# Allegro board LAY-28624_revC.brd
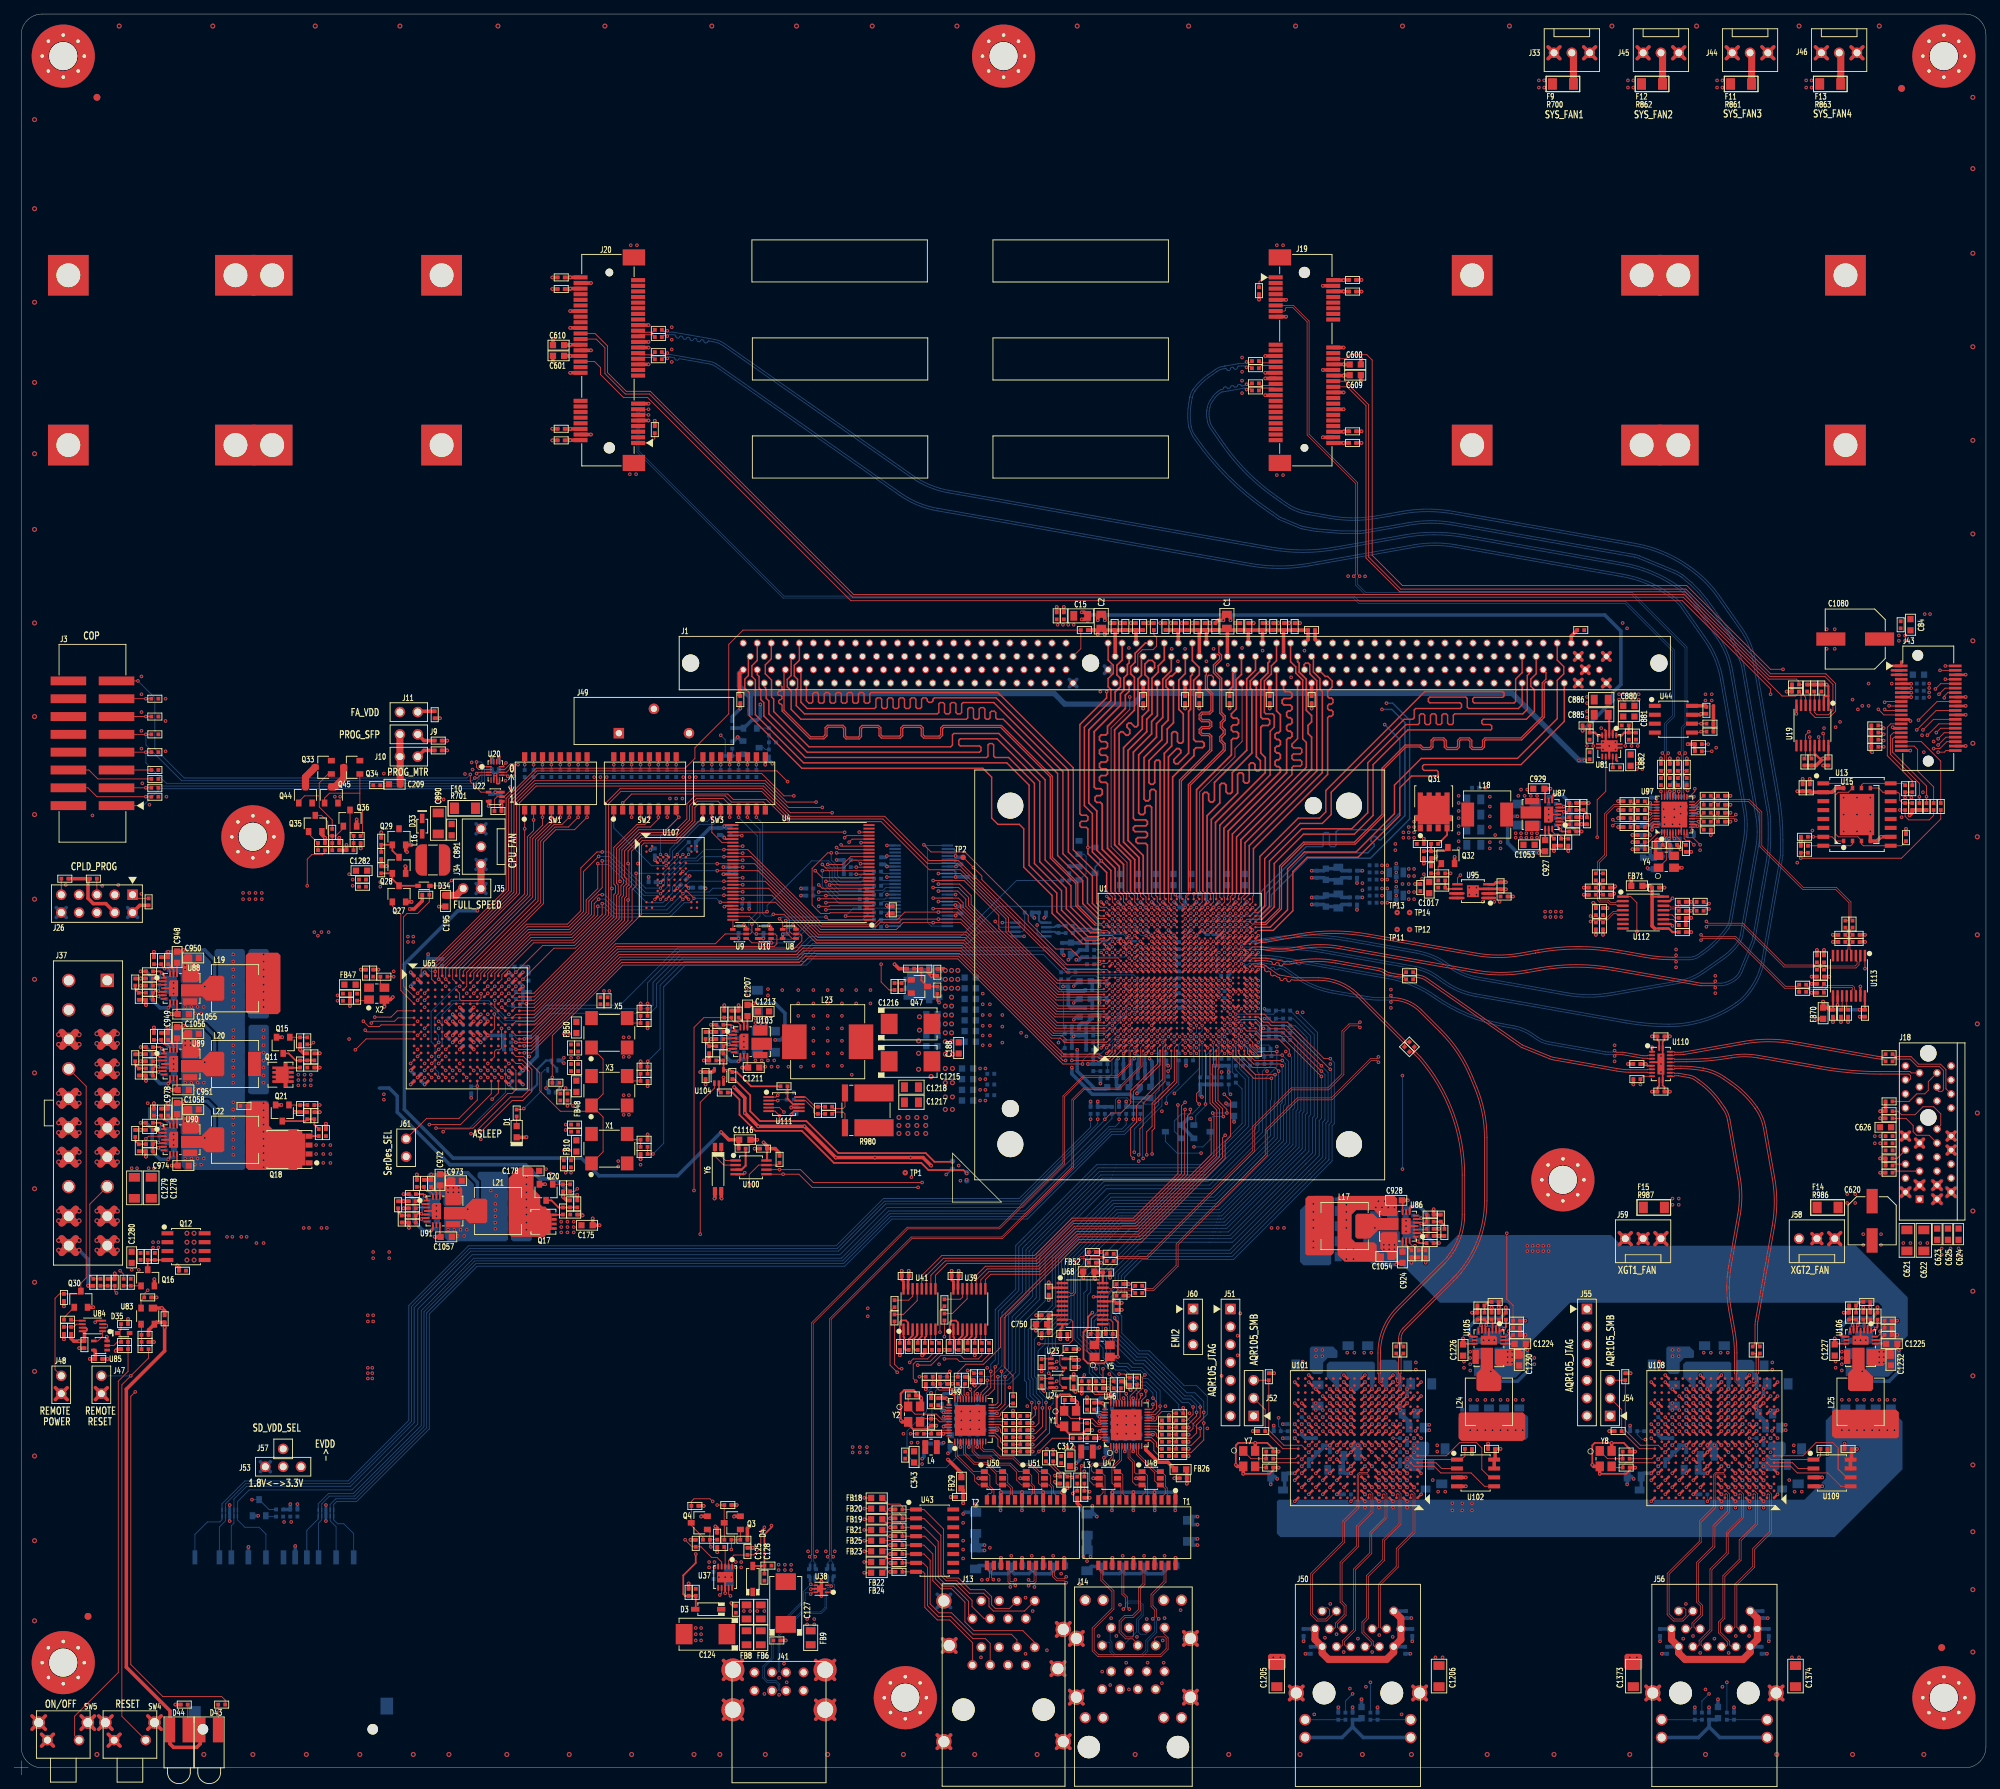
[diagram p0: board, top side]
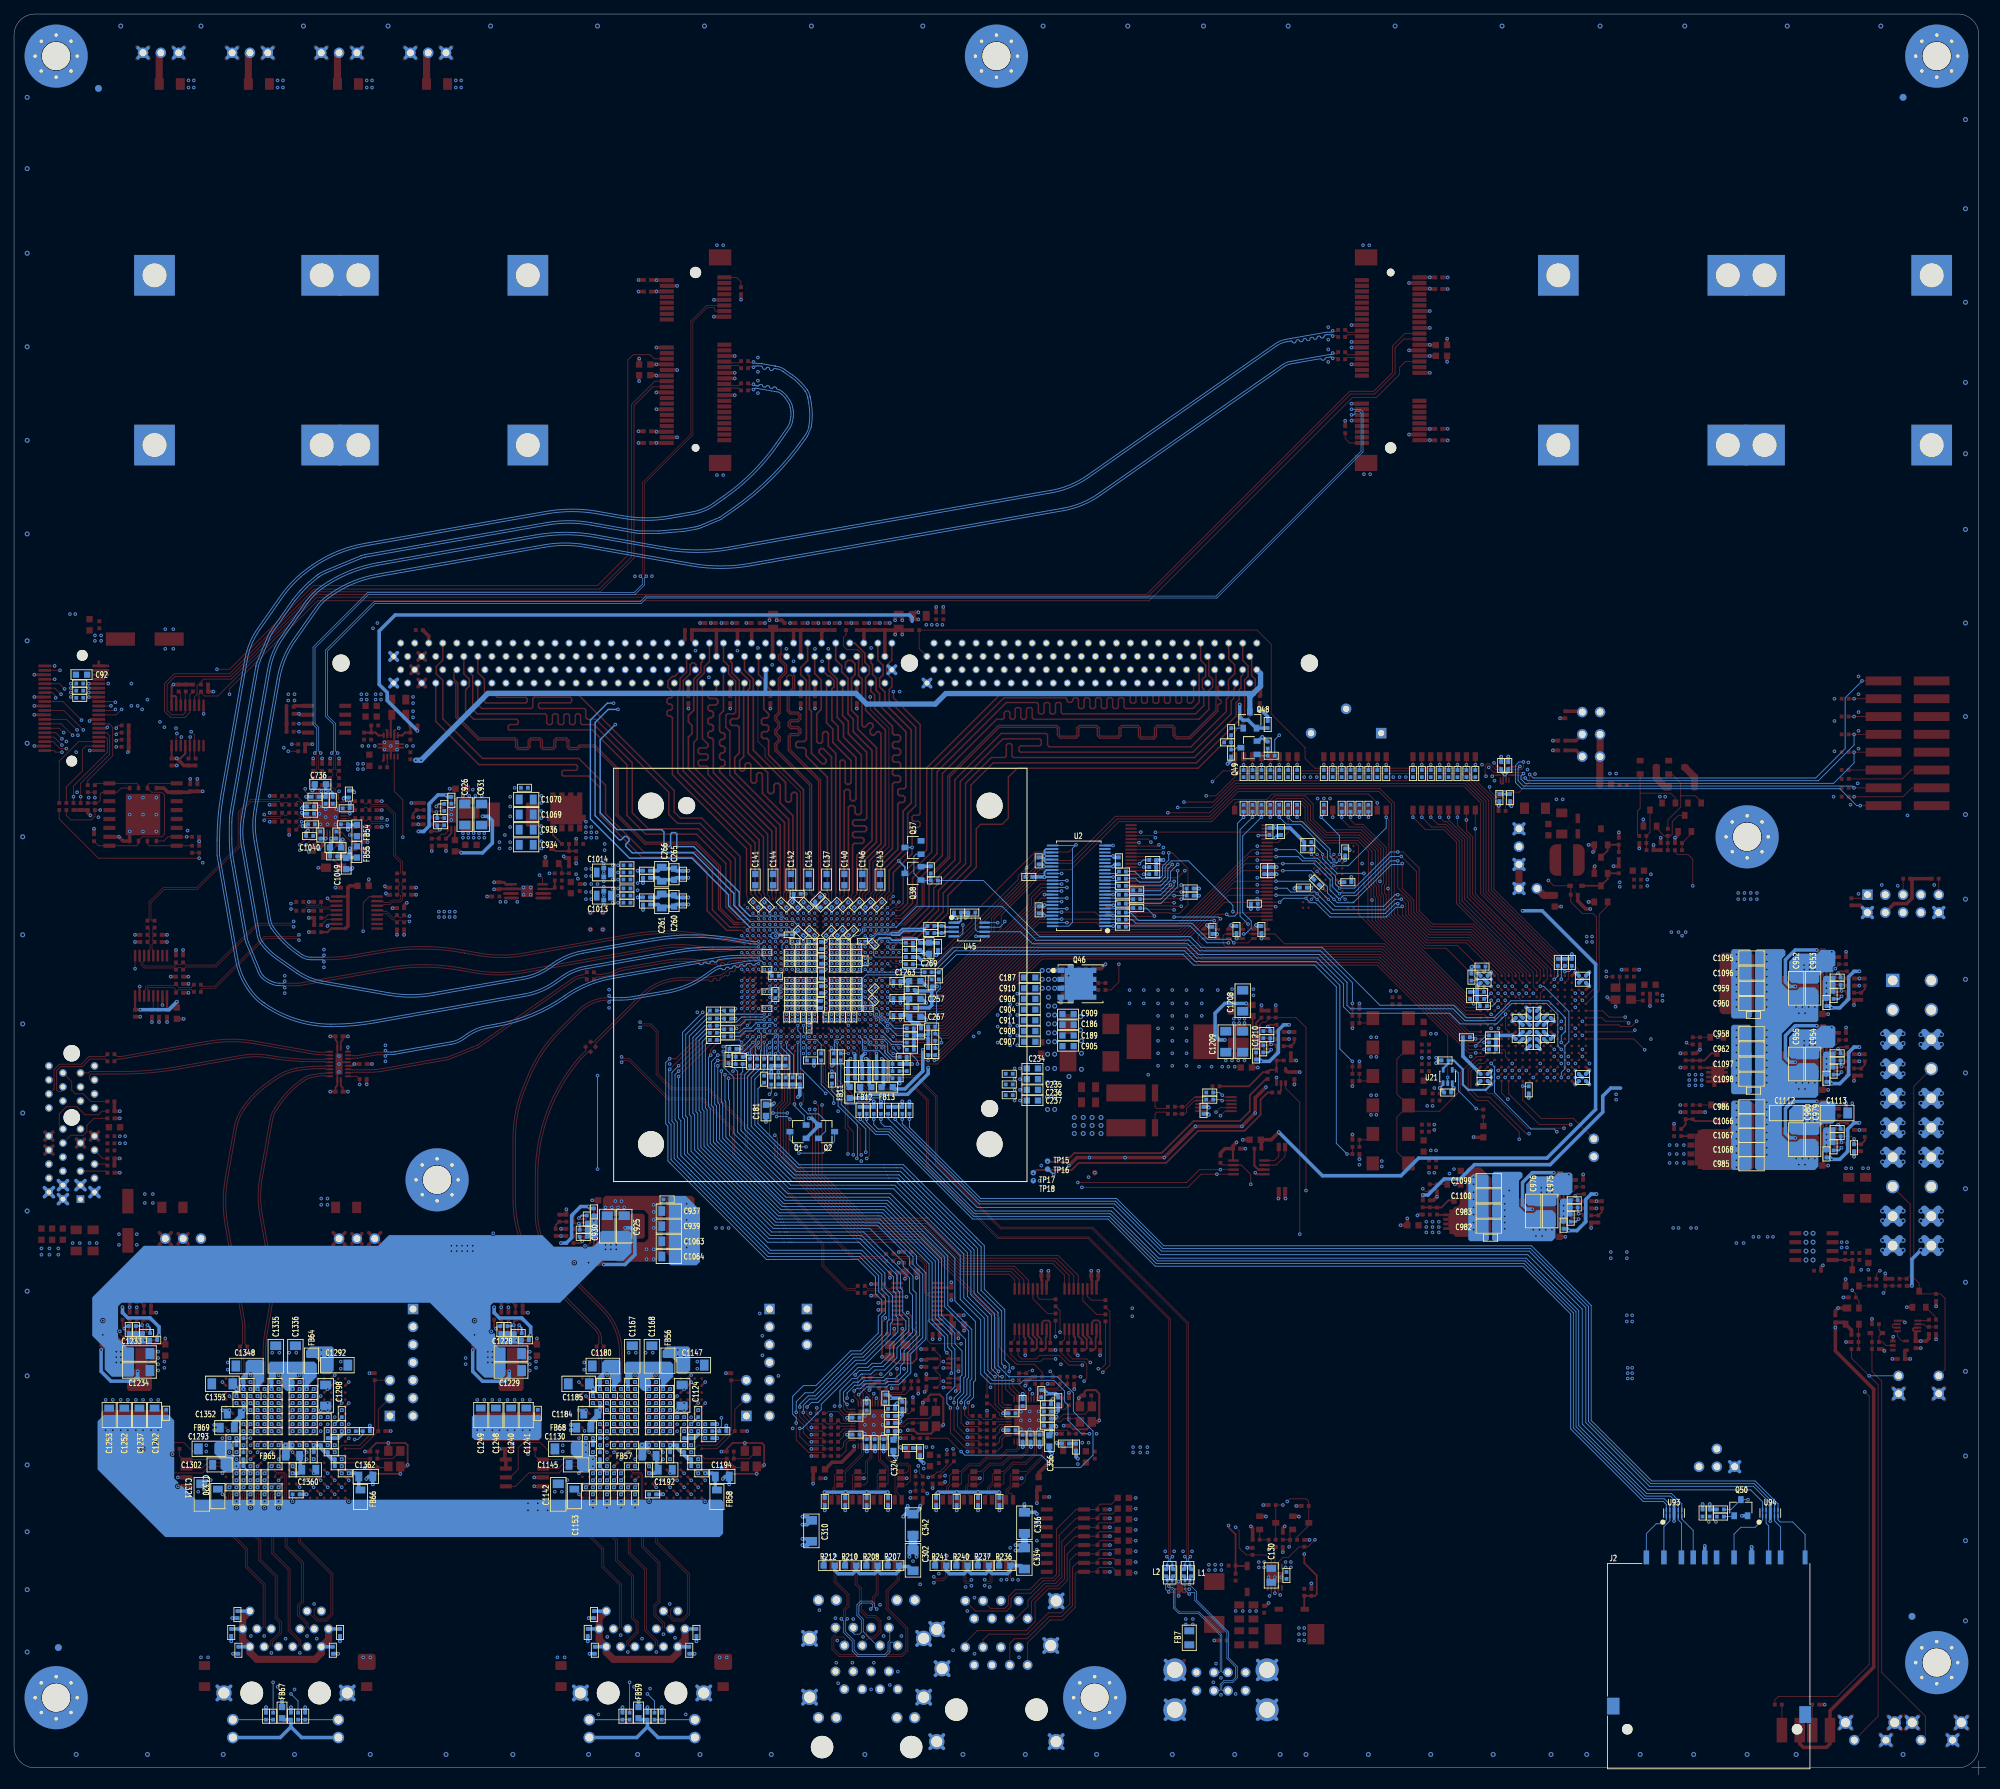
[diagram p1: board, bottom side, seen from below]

Outline 281.02 x 251.02 mm; copper layers: TOP, L2GND, L3SIG, L4PWR, L5PWR, L6SIG, L7GND, BOTTOM. Coordinates in mm from the lower left corner of the outline.
Outline path: 0,1.02 2.03,1.02 ; 1.02,2.03 1.02,0 ; 1.02,248.02 1.02,4.02 arc(1.89,1.89) 4.02,1.02 278.02,1.02 arc(280.14,1.89) 281.02,4.02 281.02,248.02 arc(280.14,250.14) 278.02,251.02 4.02,251.02 arc(1.89,250.14) 1.02,248.02

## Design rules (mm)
net group 1V05_EC1_AVDD: nets 1V05_EC1_DVDD N16973842
net group 1V05_EC2_AVDD: nets 1V05_EC2_DVDD N16880820
net group 1V8_0641_VDD: nets 1V8_0641_VDDA 1V8_0641_VDDXTAL
net group CKE_ISO_EN: nets CKE_ISO_EN N20553507
net group CPLD_REFCLK: nets CPLD_REFCLK N19163046
net group DDR_REFCLK: nets DDR_REFCLK N17232338
net group EC1_GTXCLK: nets EC1_GTXCLK N17060054
net group EC1_INT_N: nets EC1_INT_N N16974631
net group EC1_LED0: nets EC1_LED0 N16974576
net group EC1_LED1: nets EC1_LED1 N16974570
net group EC1_MDI0: nets EC1_MDI0_N EC1_MDI0_P
net group EC1_MDI1: nets EC1_MDI1_N EC1_MDI1_P
net group EC1_MDI2: nets EC1_MDI2_N EC1_MDI2_P
net group EC1_MDI3: nets EC1_MDI3_N EC1_MDI3_P
net group EC1_MDX0: nets EC1_MDX0_N EC1_MDX0_P
net group EC1_MDX1: nets EC1_MDX1_N EC1_MDX1_P
net group EC1_MDX2: nets EC1_MDX2_N EC1_MDX2_P
net group EC1_MDX3: nets EC1_MDX3_N EC1_MDX3_P
net group EC1_PME_N: nets EC1_PME_N N16975158
net group EC1_REFCLK: nets EC1_REFCLK N16975047
net group EC1_RST_N: nets EC1_RST_N N16974885
net group EC1_RXCLK: nets EC1_RXCLK N16974061
net group EC1_RXCTL: nets EC1_RXCTL N16974138
net group EC1_RXD0: nets EC1_RXD0 N16974094
net group EC1_RXD1: nets EC1_RXD1 N16974110
net group EC1_RXD2: nets EC1_RXD2 N16974123
net group EC1_RXD3: nets EC1_RXD3 N16974136
net group EC1_TXCTL: nets EC1_TXCTL N17059985
net group EC1_TXD0: nets EC1_TXD0 N17059735
net group EC1_TXD1: nets EC1_TXD1 N17059733
net group EC1_TXD2: nets EC1_TXD2 N17059734
net group EC1_TXD3: nets EC1_TXD3 N17059732
net group EC2_GTXCLK: nets EC2_GTXCLK U_EC2_GTXCLK
net group EC2_INT_N: nets EC2_INT_N N16871038
net group EC2_LED0: nets EC2_LED0 N16870898
net group EC2_LED1: nets EC2_LED1 N16870888
net group EC2_MDI0: nets EC2_MDI0_N EC2_MDI0_P
net group EC2_MDI1: nets EC2_MDI1_N EC2_MDI1_P
net group EC2_MDI2: nets EC2_MDI2_N EC2_MDI2_P
net group EC2_MDI3: nets EC2_MDI3_N EC2_MDI3_P
net group EC2_MDX0: nets EC2_MDX0_N EC2_MDX0_P
net group EC2_MDX1: nets EC2_MDX1_N EC2_MDX1_P
net group EC2_MDX2: nets EC2_MDX2_N EC2_MDX2_P
net group EC2_MDX3: nets EC2_MDX3_N EC2_MDX3_P
net group EC2_PME_N: nets EC2_PME_N N16877780
net group EC2_REFCLK: nets EC2_REFCLK N16874872
net group EC2_RST_N: nets EC2_RST_N N16873350
net group EC2_RXCLK: nets EC2_RXCLK N16869850
net group EC2_RXCTL: nets EC2_RXCTL N16869978
net group EC2_RXD0: nets EC2_RXD0 N16869910
net group EC2_RXD1: nets EC2_RXD1 N16869938
net group EC2_RXD2: nets EC2_RXD2 N16869959
net group EC2_RXD3: nets EC2_RXD3 N16869976
net group EC2_TXCTL: nets EC2_TXCTL U_EC2_TXCTL
net group EC2_TXD0: nets EC2_TXD0 U_EC2_TXD0
net group EC2_TXD1: nets EC2_TXD1 U_EC2_TXD1
net group EC2_TXD2: nets EC2_TXD2 U_EC2_TXD2
net group EC2_TXD3: nets EC2_TXD3 U_EC2_TXD3
net group EMI1_MDC_SLP: nets EMI1_MDC_SLP N17060498
net group EMI2_MDC: nets EMI2_MDC N17059643
net group ETH_REFCLK1_N: nets ETH_REFCLK1_N N24120892
net group ETH_REFCLK1_P: nets ETH_REFCLK1_P N24120812
net group ETH_REFCLK2_N: nets ETH_REFCLK2_N N24122903
net group ETH_REFCLK2_P: nets ETH_REFCLK2_P N24122905
net group EVDD_SEL: nets EVDD_SEL N20559490
net group IFC_A5: nets IFC_A5 N22257590
net group IFC_A6: nets IFC_A6 N22257592
net group IFC_A7: nets IFC_A7 N22257594
net group IFC_A8: nets IFC_A8 N22258216
net group IFC_A9: nets IFC_A9 N22258098
net group IFC_A10: nets IFC_A10 N22258100
net group IFC_A11: nets IFC_A11 N22258102
net group IFC_A12: nets IFC_A12 N22258104
net group IFC_A13: nets IFC_A13 N22258634
net group IFC_A14: nets IFC_A14 N22258636
net group IFC_A15: nets IFC_A15 N22258638
net group IFC_CLK: nets IFC_CLK IFC_CLK_R
net group INA_VCORE_N: nets INA_VCORE_N N23927714
net group INA_VCORE_P: nets INA_VCORE_P N23927707
net group IOPWR_EN: nets IOPWR_EN N18273767
net group LED_STATUS: nets LED_STATUS N22361656
net group MPEX1_REFCLK_N: nets MPEX1_REFCLK_N N23146371
net group MPEX1_REFCLK_P: nets MPEX1_REFCLK_P N23146369
net group MPEX1_RX_N: nets MPEX1_RX_N N16984265
net group MPEX1_RX_P: nets MPEX1_RX_P N16984263
net group MPEX1_TX_N: nets MPEX1_TX_N N16984233
net group MPEX1_TX_P: nets MPEX1_TX_P N16984231
net group MPEX2_REFCLK_N: nets MPEX2_REFCLK_N N23146379
net group MPEX2_REFCLK_P: nets MPEX2_REFCLK_P N23146377
net group MPEX2_RX_N: nets MPEX2_RX_N N16985388
net group MPEX2_RX_P: nets MPEX2_RX_P N16985386
net group MPEX2_TX_N: nets MPEX2_TX_N N16985356
net group MPEX2_TX_P: nets MPEX2_TX_P N16985354
net group N17055373: nets N17055373 N17055376
net group N17055394: nets N17055394 N17055396
net group N17055422: nets N17055422 N17055507
net group N17055459: nets N17055459 N17055529
net group N17055495: nets N17055419 N17055495
net group N17055527: nets N17055461 N17055527
net group N17056740: nets N17056740 N17056750
net group N17056764: nets N17056764 N17056766
net group N17056778: nets N17056778 N17056834
net group N17056796: nets N17056796 N17056846
net group N17056816: nets N17056776 N17056816
net group N17056844: nets N17056798 N17056844
net group N17321019: nets N17321001 N17321019
net group N17399246: nets N17399246 N17399288
net group N17401544: nets N17400346 N17401544
net group N18263905: nets N18263905 N18263955
net group N18271718: nets N18271718 N18271794
net group N18272820: nets N18272820 N18272905
net group N18273181: nets N18273181 N18273262
net group N18562864: nets N17523697 N18562864
net group N19623883: nets N19623883 N19623968
net group N19645019: nets N19645019 N19645035
net group N19646930: nets N19646930 N19646940
net group N19648414: nets N19648414 N19648420
net group N19650272: nets N19650272 N19650282
net group N19651731: nets N19651731 N19651747
net group N19653218: nets N19653218 N19653234
net group N20559492: nets N20559492 N20559589
net group N20559669: nets N20559669 N20559724
net group N20562350: nets N17013374 N20562350
net group N23085337: nets N23085337 N23085351
net group N23238405: nets N23238405 N23238429
net group N23398788: nets N23398788 N23398805
net group N23400099: nets N23400099 N23400105
net group N23495853: nets N23495853 N23495929
net group N23886523: nets N23886523 N23886535
net group N23926306: nets N23926306 N23926329
net group PEX_REFCLK_N: nets N23146174 PEX_REFCLK_N
net group PEX_REFCLK_P: nets N23146172 PEX_REFCLK_P
net group PEX_RX: nets PEX_RX_N PEX_RX_P
net group PEX_TX_N: nets N16980532 PEX_TX_N
net group PEX_TX_P: nets N16980534 PEX_TX_P
net group PWR_GOOD: nets N18563122 PWR_GOOD
net group SD_REFCLK1_C_N: nets SD_REFCLK1_C_N SD_REFCLK1_N
net group SD_REFCLK1_C_P: nets SD_REFCLK1_C_P SD_REFCLK1_P
net group SD_REFCLK2_C_N: nets SD_REFCLK2_C_N SD_REFCLK2_N
net group SD_REFCLK2_C_P: nets SD_REFCLK2_C_P SD_REFCLK2_P
net group SD_RX1_N: nets N23965067 SD_RX1_N
net group SD_RX1_P: nets N23965070 SD_RX1_P
net group SD_TX1: nets SD_TX1_N SD_TX1_P
net group SDHC_CLK: nets N17040868 SDHC_CLK
net group SGMII_RX: nets SGMII_RX_N SGMII_RX_P
net group SGMII_TX_N: nets N23886478 SGMII_TX_N
net group SGMII_TX_P: nets N23886479 SGMII_TX_P
net group SYS_REFCLK: nets N17170143 SYS_REFCLK
net group SYS_REFCLK_N: nets N23146565 SYS_REFCLK_N
net group SYS_REFCLK_P: nets N23146571 SYS_REFCLK_P
net group TEMP_DIODE_N: nets N18586247 TEMP_DIODE_N
net group TEMP_DIODE_P: nets N18586245 TEMP_DIODE_P
net group USB1_DM: nets N17013078 USB1_DM
net group USB1_DP: nets N17013042 USB1_DP
net group USB1_FLG_N: nets N17021121 USB1_FLG_N
net group USB2_DM: nets N17020482 USB2_DM
net group USB2_DP: nets N17020476 USB2_DP
net group USB2_FLG_N: nets N17021131 USB2_FLG_N
net group VDD_EN_N: nets N23926341 VDD_EN_N
net group VDD_SD: nets N23647021 VDD_SD
net group XFI_RX_C_N: nets XFI_RX_C_N XFI_RX_N
net group XFI_RX_C_P: nets XFI_RX_C_P XFI_RX_P
net group XFI_TX_N: nets N18848286 XFI_TX_N
net group XFI_TX_P: nets N18848288 XFI_TX_P
net group XGT1_INT_N: nets N18849311 XGT1_INT_N
net group XGT1_LED_GRN: nets N19034153 XGT1_LED_GRN
net group XGT1_LED_YEL: nets N19034241 XGT1_LED_YEL
net group XGT1_RST_N: nets N23240310 XGT1_RST_N
net group XGT2_CM: nets XGT2_CM_N XGT2_CM_P
net group XGT2_INT_N: nets N23886494 XGT2_INT_N
net group XGT2_LED_GRN: nets N23890653 XGT2_LED_GRN
net group XGT2_LED_YEL: nets N23890663 XGT2_LED_YEL
net group XGT2_MDI0: nets XGT2_MDI0_N XGT2_MDI0_P
net group XGT2_MDI1: nets XGT2_MDI1_N XGT2_MDI1_P
net group XGT2_MDI2: nets XGT2_MDI2_N XGT2_MDI2_P
net group XGT2_MDI3: nets XGT2_MDI3_N XGT2_MDI3_P
net group XGT2_RST_N: nets N23886561 XGT2_RST_N
net group XGT_CM: nets XGT1_CM_N XGT1_CM_P
net group XGT_MDI0: nets XGT1_MDI0_N XGT1_MDI0_P
net group XGT_MDI1: nets XGT1_MDI1_N XGT1_MDI1_P
net group XGT_MDI2: nets XGT1_MDI2_N XGT1_MDI2_P
net group XGT_MDI3: nets XGT1_MDI3_N XGT1_MDI3_P
net group 3V3_OSC_CPLD: nets N19163064
net group 5V0_USB1: nets USB1_VBUSCLMP
net group 5V0_USB2: nets USB2_VBUSCLMP
net group CLS_SECLK: nets EMI1_MDC TDMA_RCK_CLK8_12 TDMA_TCK_CLK9 TDMB_RCK_CLK10 TDMB_TCK_CLK11
net group DDRPWR_EN_N: nets DDRPWR_EN_N N19623885 N23495851
net group IOPWR_EN_N: nets IOPWR_EN_N N18271716 N18272822 N18273179
net group N16870294: nets N16870294 N16870296 N16870306 N16870310 N16870330
net group N16974225: nets N16974225 N16974227 N16974244 N16974248 N16974260
net group N19644936: nets N19644936 N19644956 N19645192 N19645200
net group N19646830: nets N19646830 N19646848 N19646866 N19647102
net group N19648275: nets N19648275 N19648310 N19648328 N19648572
net group N19650163: nets N19650163 N19650181 N19650199 N19650430
net group N19651628: nets N19651628 N19651646 N19651664 N19651895
net group N19653107: nets N19653107 N19653133 N19653151 N19653382
net group N23395651: nets N23395651 N23395686 N23395694 N23395911
net group N23399992: nets N23399992 N23400010 N23400026 N23400248
net group PCIE_REFCLK1_N: nets N24117707 N24120824 PCIE_REFCLK1_N
net group PCIE_REFCLK1_P: nets N24117705 N24120822 PCIE_REFCLK1_P
net group PCIE_REFCLK2_N: nets N23146387 N24122973 PCIE_REFCLK2_N
net group PCIE_REFCLK2_P: nets N23146385 N24122901 PCIE_REFCLK2_P
net group SENSEVDD: nets N18583652 SENSEGND SENSEVDD
net group SENSEVDDC: nets N18263961 N18263987 N18264015 N18264464 N18264487 N18583655 N23929117 SENSEGNDC SENSEVDDC
net group SPI_CLK: nets N16864354 N17040696 N21754633 SPI_CLK
net group SPI_MISO: nets N16864329 N21754692 SPI_MISO
net group SPI_MOSI: nets N16864338 N21754708 SPI_MOSI
net group USB_REFCLK: nets N17116912 N23147551 N23371818 N23374222 SDHC_VS USB_REFCLK

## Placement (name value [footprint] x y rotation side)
C1  22uF  [0805]  172.85 164.47 90 top
C2  22uF  [0805]  154.94 164.47 90 top
C3  0.1uF  [0402]  160.91 153.29 270 top
C4  0.1uF  [0402]  177.93 163.7 90 top
C5  0.1uF  [0402]  168.66 163.7 90 top
C6  0.1uF  [0402]  180.97 163.7 90 top
C7  0.1uF  [0402]  159.89 163.7 90 top
C8  0.1uF  [0402]  171.2 163.7 90 top
C9  0.1uF  [0402]  166.88 153.29 270 top
C10  0.1uF  [0402]  168.91 153.29 270 top
C11  0.1uF  [0402]  165.61 163.7 90 top
C12  0.1uF  [0402]  156.84 163.7 90 top
C13  0.1uF  [0402]  184.91 153.29 270 top
C14  0.1uF  [0402]  178.94 153.29 270 top
C15  22uF  [0805]  152.02 165.23 0 top
C16  0.1uF  [0402]  149.61 165.23 90 top
C17  0.1uF  [0402]  148.59 165.23 90 top
C18  0.1uF  [0402]  173.23 153.29 270 top
C19  0.1uF  [0402]  103.51 153.29 270 top
C20  0.1uF  [0402]  223.27 163.19 180 top
C21  0.1uF  [0201]  160.11 118.85 0 bottom
C22  0.01uF  [0201]  158.51 118.45 225 bottom
C23  0.1uF  [0402]  125.22 123.32 270 top
C24  0.1uF  [0402]  123.57 130.3 90 bottom
C25  0.1uF  [0402]  135 130.3 90 bottom
C26  0.1uF  [0402]  135 123.32 270 bottom
C30  0.1uF  [0402]  103.25 120.52 90 bottom
C31  0.1uF  [0402]  110.24 120.4 90 bottom
C32  0.1uF  [0402]  106.81 120.52 90 bottom
C33  1uF  [0402]  102.87 128.91 90 bottom
C34  0.1uF  [0402]  101.85 128.91 90 bottom
C35  0.1uF  [0402]  100.46 134.49 270 bottom
C36  1uF  [0402]  255.91 140.72 90 top
C37  0.1uF  [0402]  254.89 140.72 90 top
C38  1uF  [0402]  40.39 37.34 90 bottom
C39  0.1uF  [0402]  39.37 37.34 90 bottom
C48  0.1uF  [0402]  258.57 144.4 270 top
C49  0.1uF  [0402]  68.07 143.89 270 bottom
C50  0.1uF  [0402]  69.09 143.89 270 bottom
C51  0.1uF  [0402]  67.82 139.32 90 bottom
C52  0.1uF  [0402]  76.71 97.28 180 bottom
C53  0.1uF  [0402]  69.34 139.32 90 bottom
C54  0.1uF  [0402]  77.09 101.85 0 bottom
C55  10pF  [0402]  177.67 102.36 0 bottom
C56  10pF  [0402]  179.32 107.82 180 bottom
C57  0.1uF  [0402]  151 55.88 270 top
C58  0.1uF  [0402]  151 58.67 270 top
C59  0.1uF  [0402]  198.5 103.44 135 top
C60  0.1uF  [0402]  199.2 104.14 135 top
C67  0.1uF  [0402]  254.89 111.63 180 top
C68  0.1uF  [0402]  254.89 112.65 180 top
C84  0.1uF  [0603]  270.26 163.96 90 top
C85  0.01uF  [0402]  268.86 163.96 90 top
C92  10uF  [0603]  271.4 156.84 0 bottom
C93  0.1uF  [0402]  271.65 155.57 0 bottom
C94  0.1uF  [0402]  271.65 154.56 0 bottom
C124  100uF  [7343]  98.55 20.07 180 top
C125  10uF  [0805]  104.39 23.24 90 top
C126  1000pF  [0402]  102.86 23.62 90 top
C127  100uF  [7343]  109.98 24.51 90 top
C128  10uF  [0805]  106.42 23.24 90 top
C129  1000pF  [0402]  108.71 19.18 0 top
C130  10uF  [0805]  101.85 28.45 270 bottom
C131  0.1uF  [0402]  99.69 28.45 270 bottom
C132  10pF  [0402]  89.79 90.55 0 top
C133  0.1uF  [0402]  78.36 87.12 270 top
C134  0.01uF  [0402]  79.38 87.12 270 top
C135  1uF  [0402]  79.88 91.69 180 top
C136  0.1uF  [0402]  79.88 92.71 180 top
C137  10uF  [0603]  165.23 127.64 90 bottom
C138  2.2uF  [0402]  161.67 100.33 180 bottom
C139  0.01uF  [0402]  162.51 124.05 315 bottom
C140  10uF  [0603]  162.69 127.64 90 bottom
C141  10uF  [0603]  175.39 127.64 90 bottom
C142  10uF  [0603]  170.31 127.64 90 bottom
C143  10uF  [0603]  157.61 127.64 90 bottom
C144  10uF  [0603]  172.85 127.64 90 bottom
C145  10uF  [0603]  167.77 127.64 90 bottom
C146  10uF  [0603]  160.15 127.64 90 bottom
C147  0.1uF  [0201]  162.51 110.04 0 bottom
C148  0.1uF  [0201]  162.51 109.24 0 bottom
C149  2.2uF  [0402]  161.67 101.35 180 bottom
C150  0.1uF  [0402]  171.32 124.05 225 bottom
C151  0.1uF  [0402]  164.11 124.05 315 bottom
C152  0.1uF  [0402]  175.32 124.05 225 bottom
C153  0.1uF  [0402]  168.12 124.05 225 bottom
C154  0.1uF  [0402]  160.91 124.05 315 bottom
C155  0.1uF  [0402]  157.71 124.05 315 bottom
C156  0.1uF  [0402]  163.31 120.05 135 bottom
C157  0.1uF  [0402]  167.32 120.05 45 bottom
C158  0.1uF  [0201]  161.31 108.04 270 bottom
C159  0.1uF  [0201]  162.11 108.04 270 bottom
C160  3000pF  [0402]  159.64 101.35 0 bottom
C161  2.2uF  [0402]  159.64 99.31 0 bottom
C162  2.2uF  [0402]  159.64 100.33 0 bottom
C163  0.01uF  [0402]  169.72 124.05 225 bottom
C164  0.01uF  [0402]  173.72 124.05 225 bottom
C165  0.01uF  [0402]  159.31 124.05 315 bottom
C166  0.01uF  [0402]  161.71 120.05 135 bottom
C167  0.01uF  [0402]  168.92 120.05 45 bottom
C168  0.01uF  [0402]  164.92 120.05 135 bottom
C169  0.01uF  [0402]  165.72 124.05 315 bottom
C170  0.1uF  [0201]  160.91 110.04 180 bottom
C171  0.1uF  [0201]  160.91 109.24 180 bottom
C172  3000pF  [0402]  157.61 101.35 0 bottom
C173  2.2uF  [0402]  157.61 100.33 0 bottom
C174  2.2uF  [0402]  157.61 99.31 0 bottom
C175  10uF  [0603]  81.66 78.36 0 top
C176  0.1uF  [0201]  170.12 108.04 270 bottom
C177  0.1uF  [0201]  169.32 108.04 270 bottom
C178  10uF  [0603]  74.04 86.11 0 top
C179  0.1uF  [0201]  167.72 108.04 270 bottom
C180  0.1uF  [0201]  168.52 108.04 270 bottom
C181  10uF  [0603]  173.86 94.74 90 bottom
C182  0.1uF  [0201]  165.32 108.04 270 bottom
C183  0.1uF  [0201]  166.92 108.04 270 bottom
C184  0.1uF  [0201]  163.71 108.04 270 bottom
C185  0.1uF  [0201]  162.91 108.04 270 bottom
C186  10uF  [0603]  130.81 106.93 180 bottom
C187  10uF  [0603]  136.27 113.67 0 bottom
C188  10uF  [0603]  134.62 103.63 270 top
C189  10uF  [0603]  130.81 105.41 180 bottom
C192  0.1uF  [0201]  158.53 112.05 135 bottom
C195  10uF  [0603]  61.47 124.59 90 top
C196  0.1uF  [0201]  160.91 115.65 180 bottom
C197  0.1uF  [0201]  160.91 114.85 180 bottom
C198  0.1uF  [0201]  160.91 113.25 180 bottom
C199  0.1uF  [0201]  160.91 118.05 180 bottom
C200  0.1uF  [0201]  162.51 118.05 0 bottom
C201  0.1uF  [0201]  162.51 118.85 180 bottom
C202  0.1uF  [0201]  168.92 113.25 0 bottom
C203  0.1uF  [0201]  168.92 115.65 0 bottom
C204  0.1uF  [0201]  167.32 114.85 180 bottom
C205  0.1uF  [0201]  168.92 117.25 0 bottom
C206  0.1uF  [0201]  164.11 117.25 180 bottom
C207  0.1uF  [0201]  168.92 112.44 180 bottom
C208  0.1uF  [0201]  158.53 110.45 225 bottom
C209  10uF  [0603]  54.23 141.22 180 top
C210  0.1uF  [0201]  160.91 112.44 180 bottom
C211  0.1uF  [0201]  160.91 111.64 180 bottom
C212  0.1uF  [0201]  170.52 113.25 0 bottom
C213  0.1uF  [0201]  167.32 113.25 0 bottom
C214  0.1uF  [0201]  168.92 114.85 180 bottom
C215  0.1uF  [0201]  164.11 118.85 180 bottom
C216  0.1uF  [0201]  168.92 116.45 180 bottom
C217  0.1uF  [0201]  162.51 117.25 180 bottom
C218  0.1uF  [0201]  167.32 118.85 0 bottom
C219  0.1uF  [0201]  167.32 116.45 180 bottom
C220  0.1uF  [0201]  160.91 110.84 180 bottom
C222  0.1uF  [0201]  159.71 116.05 270 bottom
C223  0.1uF  [0201]  164.11 118.05 0 bottom
C224  0.1uF  [0201]  167.32 118.05 180 bottom
C225  0.1uF  [0201]  167.32 117.25 0 bottom
C226  0.1uF  [0201]  168.92 118.05 180 bottom
C227  1500pF  [0201]  167.32 115.65 0 bottom
C228  1500pF  [0201]  167.32 111.64 0 bottom
C229  1500pF  [0201]  162.51 116.45 0 bottom
C230  1500pF  [0201]  167.32 112.44 180 bottom
C232  0.1uF  [0201]  159.31 109.24 180 bottom
C234  10uF  [0603]  135.89 100.71 180 bottom
C235  10uF  [0603]  135.89 99.19 180 bottom
C236  10uF  [0603]  135.89 97.66 180 bottom
C237  10uF  [0603]  135.89 96.14 180 bottom
C238  1uF  [0402]  166.02 109.84 270 bottom
C239  1uF  [0402]  139.19 98.43 0 bottom
C240  1uF  [0402]  139.19 96.9 0 bottom
C241  1uF  [0402]  139.19 99.95 0 bottom
C242  2.2uF  [0402]  193.67 126.37 180 bottom
C243  2.2uF  [0402]  193.67 124.33 180 bottom
C244  3000pF  [0402]  193.67 125.35 180 bottom
C245  0.1uF  [0201]  169.72 118.85 180 bottom
C246  0.1uF  [0201]  170.52 117.25 0 bottom
C247  0.1uF  [0201]  170.52 116.45 0 bottom
C248  0.1uF  [0201]  170.52 115.65 0 bottom
C249  2.2uF  [0402]  193.67 128.65 180 bottom
C250  2.2uF  [0402]  193.67 129.67 180 bottom
C251  3000pF  [0402]  193.67 127.64 180 bottom
C252  0.1uF  [0201]  173.73 111.65 0 bottom
C253  0.1uF  [0201]  173.72 114.85 0 bottom
C254  0.1uF  [0201]  170.56 119.76 180 bottom
C255  0.1uF  [0201]  173.72 117.25 0 bottom
C257  10uF  [0603]  152.65 110.62 180 bottom
C258  1uF  [0402]  155.19 110.74 0 bottom
C259  3000pF  [0402]  185.67 124.59 90 bottom
C260  4.7uF  [0603]  186.94 124.59 90 bottom
C261  47uF  [0805]  188.72 124.59 90 bottom
C264  3000pF  [0402]  185.67 128.4 90 bottom
C265  4.7uF  [0603]  186.94 128.4 90 bottom
C266  47uF  [0805]  188.72 128.4 90 bottom
C267  10uF  [0603]  152.65 108.08 180 bottom
C268  1uF  [0402]  155.19 108.33 0 bottom
C269  10uF  [0603]  150.62 117.86 270 bottom
C270  1uF  [0402]  151.89 118.11 270 bottom
C271  0.1uF  [0402]  134.62 61.09 270 top
C272  0.1uF  [0402]  134.11 71.12 0 top
C273  0.1uF  [0402]  133.35 61.09 270 top
C274  0.1uF  [0402]  135.89 61.09 270 top
C275  0.1uF  [0402]  136.91 61.09 270 top
C276  100pF  [0402]  126.11 34.04 180 top
C277  100pF  [0402]  126.11 36.58 180 top
C278  100pF  [0402]  126.11 35.31 180 top
C279  100pF  [0402]  126.11 37.85 180 top
C284  0.1uF  [0402]  128.78 61.09 270 top
C285  0.1uF  [0402]  127.51 61.09 270 top
C286  0.1uF  [0402]  127 71.12 0 top
C287  0.1uF  [0402]  126.24 61.09 270 top
C288  0.1uF  [0402]  129.79 61.09 270 top
C289  100pF  [0402]  126.11 32.77 180 top
C290  100pF  [0402]  126.11 28.96 180 top
C291  100pF  [0402]  126.11 31.5 180 top
C292  100pF  [0402]  126.11 30.23 180 top
C293  0.1uF  [0402]  241.17 151.76 270 top
C294  1000pF  [0402]  148.84 120.52 90 bottom
C295  0.1uF  [0402]  146.56 122.94 0 bottom
C296  0.01uF  [0402]  156.46 38.99 90 bottom
C297  0.1uF  [0402]  166.62 42.29 180 top
C298  0.01uF  [0402]  159.51 38.99 90 bottom
C299  0.01uF  [0402]  162.56 38.99 90 bottom
C300  10pF  [0402]  164.08 50.55 180 top
C301  0.01uF  [0402]  165.48 38.99 90 bottom
C302  1000pF  [1206]  152.91 30.61 90 bottom
C303  10pF  [0402]  153.42 48.01 0 top
C304  4.7pF  [0402]  150.24 53.47 0 top
C305  4.7pF  [0402]  152.91 49.66 270 top
C307  470pF  [0402]  151.51 40 270 top
C308  470pF  [0402]  152.53 40 270 top
C309  1000pF  [0402]  151.89 46.1 270 bottom
C310  1000pF  [1206]  167.39 34.8 270 bottom
C312  4.7uF  [0603]  150.5 44.83 270 top
C313  0.1uF  [0402]  149.22 44.96 270 top
C314  0.1uF  [0402]  161.04 48.51 180 bottom
C315  0.1uF  [0402]  161.04 50.93 180 bottom
C316  0.1uF  [0402]  156.84 53.72 270 bottom
C317  0.1uF  [0402]  159.51 52.45 270 bottom
C319  0.1uF  [0402]  155.96 50.16 0 bottom
C320  0.1uF  [0402]  155.96 52.2 0 bottom
C321  0.1uF  [0402]  159.51 47.37 90 bottom
C322  0.1uF  [0402]  155.96 51.18 0 bottom
C323  0.1uF  [0402]  157.1 47.37 90 bottom
C324  4.7uF  [0603]  155.7 46.99 270 bottom
C325  0.1uF  [0402]  155.96 49.02 0 bottom
C326  0.1uF  [0402]  158.37 47.37 90 bottom
C328  0.01uF  [0402]  140.59 38.99 90 bottom
C329  0.1uF  [0402]  134.75 39.62 180 top
C330  0.01uF  [0402]  143.64 38.99 90 bottom
C331  10pF  [0402]  141.86 51.18 180 top
C332  0.01uF  [0402]  146.69 38.99 90 bottom
C333  0.01uF  [0402]  149.61 38.99 90 bottom
C334  1000pF  [1206]  137.03 30.86 90 bottom
C335  10pF  [0402]  131.19 48.64 0 top
C336  1000pF  [1206]  137.03 35.94 270 bottom
C337  470pF  [0402]  150.11 42.04 270 top
C338  470pF  [0402]  149.1 42.04 270 top
C339  4.7pF  [0402]  128.02 54.1 0 top
C340  4.7pF  [0402]  130.68 50.29 270 top
C341  1000pF  [0402]  129.67 46.74 270 bottom
C342  1000pF  [1206]  152.91 35.69 270 bottom
C343  4.7uF  [0603]  128.27 45.34 270 top
C344  0.1uF  [0402]  127 45.59 270 top
C346  0.1uF  [0402]  138.81 51.56 180 bottom
C347  0.1uF  [0402]  138.81 49.15 180 bottom
C348  0.1uF  [0402]  137.29 53.09 270 bottom
C349  0.1uF  [0402]  134.62 54.36 270 bottom
C350  0.1uF  [0402]  133.73 50.8 0 bottom
C351  0.1uF  [0402]  133.73 52.83 0 bottom
C353  0.1uF  [0402]  137.29 48.01 90 bottom
C354  0.1uF  [0402]  134.87 48.01 90 bottom
C355  0.1uF  [0402]  133.73 51.82 0 bottom
C356  4.7uF  [0603]  133.48 47.62 270 bottom
C357  0.1uF  [0402]  133.73 49.78 0 bottom
C358  0.1uF  [0402]  136.14 48.01 90 bottom
C598  0.1uF  [0402]  176.91 197.36 180 top
C599  0.1uF  [0402]  176.91 198.37 180 top
C600  10uF  [0603]  191.13 201.06 0 top
C601  10uF  [0603]  77.6 202.29 180 top
C602  0.1uF  [0402]  190.75 189.88 0 top
C603  0.1uF  [0402]  190.75 213.11 0 top
C604  0.1uF  [0402]  77.98 190.25 180 top
C605  0.1uF  [0402]  77.98 213.47 180 top
C606  0.1uF  [0402]  267.21 102.74 180 top
C607  0.1uF  [0402]  267.21 101.73 180 top
C609  10uF  [0603]  191.13 199.53 0 top
C610  10uF  [0603]  77.6 203.82 180 top
C611  0.1uF  [0402]  190.75 211.45 0 top
C612  0.1uF  [0402]  190.75 191.53 0 top
C613  0.1uF  [0402]  77.98 211.82 180 top
C614  0.1uF  [0402]  77.98 191.9 180 top
C620  100uF  [CAPE_B6D3]  264.8 78.99 270 top
C621  10uF  [1206]  269.75 76.2 270 top
C622  10uF  [1206]  272.16 76.2 270 top
C623  0.1uF  [0603]  274.07 77.09 270 top
C624  0.1uF  [0603]  277.11 77.09 270 top
C625  0.1uF  [0603]  275.59 77.09 270 top
C626  10uF  [0603]  266.7 92.33 180 top
C627  0.1uF  [0402]  267.21 91.06 180 top
C628  0.1uF  [0402]  267.21 90.04 180 top
C629  0.1uF  [0402]  267.21 89.03 180 top
C630  0.1uF  [0402]  91.82 205.99 0 top
C631  0.1uF  [0402]  91.82 204.98 0 top
C698  1uF  [0402O]  65.52 106.93 180 bottom
C699  0.1uF  [0402O]  63.52 105.93 0 bottom
C700  0.1uF  [0402O]  63.52 106.93 180 bottom
C701  0.1uF  [0402]  47.37 110.36 0 top
C702  0.01uF  [0402]  47.37 111.38 0 top
C703  1uF  [0402]  50.16 114.3 90 top
C704  0.1uF  [0402]  51.18 114.3 90 top
C705  1uF  [0402O]  57.51 112.93 0 bottom
C706  0.1uF  [0402O]  62.51 107.93 0 bottom
C707  0.1uF  [0402O]  57.51 99.92 0 bottom
C708  0.1uF  [0402O]  57.51 98.92 180 bottom
C709  0.1uF  [0402O]  62.51 104.92 0 bottom
C710  0.1uF  [0402O]  71.52 98.92 0 bottom
C711  1uF  [0402O]  64.02 108.43 270 bottom
C712  0.1uF  [0402O]  65.02 108.43 270 bottom
C713  0.1uF  [0402O]  71.52 99.92 180 bottom
C714  0.1uF  [0402O]  66.52 107.93 180 bottom
C715  0.1uF  [0402O]  57.51 113.93 180 bottom
C716  0.1uF  [0402O]  66.52 104.92 180 bottom
C718  10pF  [0402]  89.79 98.93 0 top
C720  0.1uF  [0402]  78.87 96.65 270 top
C721  0.01uF  [0402]  77.85 96.65 270 top
C722  1uF  [0402]  79.38 100.84 90 top
C723  0.1uF  [0402]  80.39 100.84 90 top
C728  10pF  [0402]  89.79 107.19 0 top
C729  0.1uF  [0402]  79.38 103.63 270 top
C730  0.01uF  [0402]  80.39 103.63 270 top
C731  1uF  [0402]  83.57 110.36 90 top
C732  0.1uF  [0402]  84.58 110.36 90 top
C733  2pF  [0402]  234.44 132.59 180 top
C734  2pF  [0402]  236.47 132.59 0 top
C735  0.1uF  [0402]  238.89 133.86 180 bottom
C736  10uF  [0603]  237.36 141.22 0 bottom
C737  0.01uF  [0402]  236.6 138.94 270 bottom
C738  4.7pF  [0402]  156.08 62.86 180 top
C739  4.7pF  [0402]  153.92 62.86 0 top
C742  0.1uF  [0402]  157.1 66.8 270 top
C743  0.1uF  [0402]  149.61 62.86 0 top
C746  0.1uF  [0402]  155.7 71.63 0 top
C747  0.1uF  [0402]  147.45 68.96 270 top
C750  10uF  [0603]  146.43 64.26 180 top
C751  0.01uF  [0402]  146.94 65.53 180 top
C873  0.01uF  [0402]  41.78 102.36 270 top
C874  0.01uF  [0402]  20.07 73.91 270 top
C875  0.01uF  [0402]  79.25 81.41 270 top
C876  0.01uF  [0402]  41.78 93.98 270 top
C880  10uF  [0603]  230.12 152.4 0 top
C881  10uF  [0603]  230.12 150.88 0 top
C882  4.7uF  [0603]  230.38 144.65 90 top
C883  0.1uF  [0402]  224.54 145.29 90 top
C884  1uF  [0402]  224.54 148.08 270 top
C885  22uF  [0805]  226.19 151.13 180 top
C886  22uF  [0805]  226.19 153.29 180 top
C887  1000pF  [0402]  230.12 148.08 270 top
C890  10uF  [1206]  60.45 135.64 270 top
C891  0.1uF  [0603]  62.36 134.75 270 top
C892  22pF  [0402]  52.32 133.1 90 top
C893  0.1uF  [0402]  18.67 61.72 0 top
C894  0.1uF  [0402]  14.35 70.23 90 top
C895  0.1uF  [0402]  15.75 64.26 0 top
C896  0.1uF  [0402]  7.11 63.37 270 top
C897  0.1uF  [0402]  12.06 59.31 0 top
C898  0.1uF  [0402]  10.03 61.34 270 top
C904  10uF  [0603]  136.27 109.09 0 bottom
C905  10uF  [0603]  130.81 103.89 180 bottom
C906  10uF  [0603]  136.27 110.62 0 bottom
C907  10uF  [0603]  136.27 104.52 0 bottom
C908  10uF  [0603]  136.27 106.05 0 bottom
C909  10uF  [0603]  130.81 108.46 180 bottom
C910  10uF  [0603]  136.27 112.14 0 bottom
C911  10uF  [0603]  136.27 107.57 0 bottom
C912  1uF  [0402]  166.02 116.15 270 bottom
C913  1uF  [0402]  166.02 118.25 90 bottom
C914  1uF  [0402]  166.02 111.94 270 bottom
C915  1uF  [0402]  166.02 114.05 270 bottom
C916  0.1uF  [0201]  167.32 110.04 0 bottom
C917  0.1uF  [0201]  168.92 111.64 0 bottom
C918  0.1uF  [0201]  167.32 110.84 180 bottom
C919  0.1uF  [0201]  168.92 110.84 180 bottom
C920  1500pF  [0201]  164.11 110.04 180 bottom
C921  1500pF  [0201]  164.11 110.84 0 bottom
C922  1500pF  [0201]  162.51 110.84 0 bottom
C923  1500pF  [0201]  162.51 112.44 0 bottom
C924  0.33uF  [0603]  197.87 73.79 270 top
C925  22uF  [1206]  194.06 78.23 90 bottom
C926  22uF  [1206]  216.79 136.91 90 bottom
C927  0.47uF  [0603]  218.19 132.46 270 top
C928  1uF  [0603]  196.98 81.92 0 top
C929  1uF  [0603]  217.3 140.59 0 top
C930  22uF  [1206]  196.47 78.23 90 bottom
C931  22uF  [1206]  214.38 136.91 90 bottom
C932  1uF  [0402]  221.49 132.97 90 top
C933  0.1uF  [0402]  187.96 82.04 0 bottom
C934  47uF  [0805]  208.03 132.59 0 bottom
C935  0.1uF  [0402]  203.33 79.38 270 top
C936  47uF  [0805]  208.03 134.75 0 bottom
C937  47uF  [0805]  187.71 80.39 0 bottom
C938  0.01uF  [0402]  201.17 74.3 90 top
C939  47uF  [0805]  187.71 78.23 0 bottom
C940  0.1uF  [0402]  208.28 140.72 0 bottom
C941  0.1uF  [0402]  223.65 138.05 270 top
C942  470pF  [0402]  201.8 78.87 0 top
C943  560pF  [0402]  222.12 137.54 0 top
C944  1uF  [0402]  198.37 80.26 270 bottom
C945  0.01uF  [0402]  199.39 79.25 270 bottom
C946  1uF  [0402]  218.69 138.94 270 bottom
C947  0.1uF  [0402]  219.71 137.92 270 bottom
C948  0.47uF  [0603]  23.24 116.59 90 top
C949  0.47uF  [0603]  23.24 105.79 90 top
C950  1uF  [0603]  25.53 116.46 180 top
C951  1uF  [0603]  24.13 97.66 180 top
C952  22uF  [1206]  27.05 112.14 270 bottom
C953  22uF  [1206]  24.64 112.14 270 bottom
C954  22uF  [1206]  24.64 101.35 270 bottom
C955  22uF  [1206]  27.05 101.35 270 bottom
C956  0.01uF  [0402]  19.94 116.08 270 top
C957  0.01uF  [0402]  19.94 105.28 270 top
C958  47uF  [0805]  33.4 105.66 180 bottom
C959  47uF  [0805]  33.4 112.14 180 bottom
C960  47uF  [0805]  33.4 109.98 180 bottom
C961  0.1uF  [0402]  33.15 108.33 180 bottom
C962  47uF  [0805]  33.4 103.51 180 bottom
C963  0.1uF  [0402]  33.15 97.54 180 bottom
C964  0.1uF  [0402]  17.78 111 90 top
C965  0.1uF  [0402]  17.78 100.2 90 top
C966  560pF  [0402]  19.3 111.51 180 top
C967  620pF  [0402]  19.3 100.71 180 top
C968  1uF  [0402]  22.73 110.11 90 bottom
C969  0.01uF  [0402]  21.72 111.12 90 bottom
C970  1uF  [0402]  22.73 99.31 90 bottom
C971  0.01uF  [0402]  21.72 100.33 90 bottom
C972  1uF  [0603]  60.71 84.84 90 top
C973  1uF  [0603]  62.99 84.71 180 top
C974  1uF  [0603]  24.13 86.87 180 top
C975  22uF  [1206]  62.1 80.39 270 bottom
C976  22uF  [1206]  64.52 80.39 270 bottom
C977  0.01uF  [0402]  57.4 84.33 270 top
C978  1uF  [0603]  23.24 95 90 top
C979  22uF  [1206]  24.64 90.55 270 bottom
C980  22uF  [1206]  27.05 90.55 270 bottom
C981  0.01uF  [0402]  19.94 94.49 270 top
C982  47uF  [0805]  70.87 78.23 180 bottom
C983  47uF  [0805]  70.87 80.39 180 bottom
C984  0.1uF  [0402]  70.61 76.58 180 bottom
C985  47uF  [0805]  33.4 87.12 180 bottom
C986  47uF  [0805]  33.4 95.25 180 bottom
C987  0.1uF  [0402]  32.77 95.38 180 top
C988  0.1uF  [0402]  55.24 79.25 90 top
C989  0.1uF  [0402]  17.78 89.41 90 top
C990  680pF  [0402]  56.77 79.76 180 top
C991  680pF  [0402]  19.3 89.92 180 top
C992  1uF  [0402]  60.2 78.36 90 bottom
C993  0.01uF  [0402]  59.18 79.38 90 bottom
C994  1uF  [0402]  22.73 88.52 90 bottom
C995  0.01uF  [0402]  21.72 89.54 90 bottom
C996  0.01uF  [0402]  201.93 131.19 90 top
C998  0.1uF  [0402]  175.89 163.7 90 top
C999  0.1uF  [0402]  184.91 163.19 0 top
C1002  0.1uF  [0402]  21.46 65.02 90 top
C1003  1500pF  [0201]  164.11 116.45 0 bottom
C1004  1500pF  [0201]  170.52 110.84 180 bottom
C1005  1500pF  [0201]  168.92 109.24 180 bottom
C1006  1500pF  [0201]  167.32 109.24 180 bottom
C1007  1500pF  [0201]  164.11 114.85 0 bottom
C1008  1500pF  [0201]  162.51 114.85 0 bottom
C1009  1500pF  [0201]  164.11 115.65 180 bottom
C1010  1500pF  [0201]  162.51 115.65 180 bottom
C1011  0.1uF  [0201]  160.91 117.25 180 bottom
C1012  0.1uF  [0201]  160.91 116.45 180 bottom
C1013  NFM21PC225B0J3  [NFM21]  196.98 125.35 0 bottom
C1014  NFM21PC225B0J3  [NFM21]  196.98 128.65 180 bottom
C1015  1uF  [0402]  212.34 125.22 0 top
C1016  1uF  [0402]  211.84 126.75 270 top
C1017  10uF  [0603]  201.68 126.49 90 top
C1022  0.1uF  [0402]  155.32 100.33 180 bottom
C1023  0.01uF  [0402]  45.85 132.84 180 top
C1024  0.01uF  [0402]  48.89 132.84 0 top
C1026  0.1uF  [0201]  173.72 109.24 0 bottom
C1027  0.1uF  [0201]  170.52 112.44 180 bottom
C1028  0.1uF  [0201]  164.51 108.04 270 bottom
C1029  0.1uF  [0201]  164.11 113.25 180 bottom
C1030  0.1uF  [0201]  164.11 112.44 0 bottom
C1031  0.1uF  [0201]  162.51 111.64 180 bottom
C1032  0.1uF  [0201]  164.11 111.64 180 bottom
C1033  0.1uF  [0201]  164.11 109.24 0 bottom
C1034  0.1uF  [0201]  170.52 109.24 180 bottom
C1035  0.1uF  [0201]  162.51 113.25 180 bottom
C1036  0.1uF  [0201]  170.92 108.04 270 bottom
C1037  0.1uF  [0201]  170.52 111.64 0 bottom
C1038  0.1uF  [0201]  170.52 110.04 0 bottom
C1039  0.1uF  [0201]  168.92 110.04 0 bottom
C1040  10uF  [0603]  235.2 132.21 180 bottom
C1041  0.01uF  [0402]  235.08 133.98 90 bottom
C1044  0.1uF  [0402]  238.76 138.05 180 bottom
C1045  0.1uF  [0402]  235.58 138.94 270 bottom
C1046  0.1uF  [0402]  233.68 137.79 0 bottom
C1047  0.1uF  [0402]  233.93 135.51 0 bottom
C1048  0.1uF  [0402]  238.63 135.51 180 bottom
C1049  10uF  [0603]  233.68 129.92 270 bottom
C1050  0.1uF  [0402]  238.76 137.03 180 bottom
C1051  0.1uF  [0402]  233.3 139.83 90 bottom
C1052  0.1uF  [0402]  237.36 133.98 90 bottom
C1053  1uF  [0603]  215.9 132.59 0 top
C1054  1uF  [0603]  195.58 73.91 0 top
C1055  1uF  [0603]  24.13 108.46 180 top
C1056  1uF  [0603]  25.53 105.66 180 top
C1057  1uF  [0603]  61.59 76.71 180 top
C1058  1uF  [0603]  25.53 94.87 180 top
C1063  47uF  [0805]  187.71 76.07 0 bottom
C1064  47uF  [0805]  187.71 73.91 0 bottom
C1066  47uF  [0805]  33.4 93.22 180 bottom
C1067  47uF  [0805]  33.4 91.19 180 bottom
C1068  47uF  [0805]  33.4 89.15 180 bottom
C1069  47uF  [0805]  208.03 136.91 0 bottom
C1070  47uF  [0805]  208.03 139.06 0 bottom
C1079  0.1uF  [0402]  200.41 126.49 90 top
C1080  220uF  [CAPE_B8]  262.38 161.92 180 top
C1081  0.1uF  [0402]  271.65 153.54 0 bottom
C1095  47uF  [0805]  33.4 116.46 180 bottom
C1096  47uF  [0805]  33.4 114.3 180 bottom
C1097  47uF  [0805]  33.4 101.35 180 bottom
C1098  47uF  [0805]  33.4 99.19 180 bottom
C1099  47uF  [0805]  70.87 84.71 180 bottom
C1100  47uF  [0805]  70.87 82.55 180 bottom
C1101  0.1uF  [0402O]  65.52 105.93 0 bottom
C1102  0.1uF  [0402O]  64.02 104.42 90 bottom
C1103  0.1uF  [0402O]  65.02 104.42 90 bottom
C1104  0.1uF  [0402O]  71.52 112.93 180 bottom
C1105  0.1uF  [0402O]  71.52 113.93 0 bottom
C1112  22uF  [1206]  28.45 94.36 0 bottom
C1113  22uF  [1206]  21.21 94.36 180 bottom
C1114  0.1uF  [0201]  167.72 106.45 270 bottom
C1115  0.1uF  [0402]  106.81 89.28 180 top
C1116  10uF  [0603]  104.14 90.55 0 top
C1117  0.1uF  [0402]  196.98 60.58 270 top
C1118  0.1uF  [0402]  197.99 60.58 270 top
C1119  18pF  [0402]  178.94 46.1 0 top
C1120  18pF  [0402]  178.94 43.81 0 top
C1121  1uF  [0402]  210.57 46.48 180 top
C1122  2.2uF  [0402]  188.01 49.01 180 bottom
C1123  2.2uF  [0402]  195.02 47.01 0 bottom
C1124  100uF  [1206]  185.8 54.1 90 bottom
C1125  2.2uF  [0402]  193.02 47.01 0 bottom
C1126  2.2uF  [0402]  196.52 42.5 270 bottom
C1127  2.2uF  [0402]  195.52 42.5 90 bottom
C1128  2.2uF  [0402]  194.52 42.5 270 bottom
C1129  2.2uF  [0402]  193.02 44 0 bottom
C1130  100uF  [1206]  202.44 46.48 0 bottom
C1131  2.2uF  [0402]  195.02 52.01 0 bottom
C1132  2.2uF  [0402]  190.01 53.01 180 bottom
C1133  2.2uF  [0402]  188.01 51.01 180 bottom
C1134  2.2uF  [0402]  195.02 49.01 180 bottom
C1135  2.2uF  [0402]  193.02 49.01 180 bottom
C1136  2.2uF  [0402]  197.02 41 0 bottom
C1137  2.2uF  [0402]  195.02 41 0 bottom
C1138  2.2uF  [0402]  192.52 39.5 90 bottom
C1139  2.2uF  [0402]  194.52 39.5 90 bottom
C1140  2.2uF  [0402]  196.52 39.5 90 bottom
C1141  2.2uF  [0402]  198.52 39.5 90 bottom
C1142  100uF  [1206]  203.45 40 90 bottom
C1143  2.2uF  [0402]  193.02 52.01 0 bottom
C1144  2.2uF  [0402]  195.02 51.01 180 bottom
C1145  47uF  [0805]  200.91 44.2 0 bottom
C1146  2.2uF  [0402]  190.01 49.01 180 bottom
C1147  100uF  [1206]  184.15 58.42 180 bottom
C1148  2.2uF  [0402]  188.01 50.01 0 bottom
C1149  2.2uF  [0402]  197.52 42.5 90 bottom
C1150  2.2uF  [0402]  190.01 47.01 0 bottom
C1151  2.2uF  [0402]  199.02 41 0 bottom
C1152  2.2uF  [0402]  193.02 41 0 bottom
C1153  47uF  [0805]  201.17 39.75 90 bottom
C1154  2.2uF  [0402]  196.52 52.51 90 bottom
C1155  2.2uF  [0402]  196.52 49.51 270 bottom
C1156  2.2uF  [0402]  195.02 53.01 180 bottom
C1157  2.2uF  [0402]  190.01 54.01 0 bottom
C1158  2.2uF  [0402]  190.01 52.01 0 bottom
C1159  2.2uF  [0402]  190.01 51.01 180 bottom
C1160  0.01uF  [0402]  188.01 55.01 180 bottom
C1161  0.01uF  [0402]  193.02 55.01 180 bottom
C1162  0.01uF  [0402]  190.01 55.01 180 bottom
C1163  0.01uF  [0402]  196.02 54.01 180 bottom
C1164  0.1uF  [0402]  190.01 56.01 180 bottom
C1165  0.1uF  [0402]  193.02 56.01 180 bottom
C1166  2.2uF  [0402]  190.01 50.01 0 bottom
C1167  100uF  [1206]  192.91 59.69 90 bottom
C1168  100uF  [1206]  190.12 59.69 90 bottom
C1169  2.2uF  [0402]  193.02 54.01 0 bottom
C1170  2.2uF  [0402]  193.02 53.01 180 bottom
C1171  2.2uF  [0402]  188.01 54.01 0 bottom
C1172  2.2uF  [0402]  188.01 53.01 180 bottom
C1173  2.2uF  [0402]  188.01 52.01 0 bottom
C1174  2.2uF  [0402]  193.02 50.01 0 bottom
C1175  2.2uF  [0402]  195.02 50.01 0 bottom
C1176  2.2uF  [0402]  193.02 51.01 180 bottom
C1177  0.01uF  [0402]  195.02 55.01 180 bottom
C1178  0.01uF  [0402]  197.02 55.01 180 bottom
C1179  0.1uF  [0402]  197.02 56.01 180 bottom
C1180  100uF  [1206]  197.1 58.29 0 bottom
C1181  2.2uF  [0402]  198.02 54.01 180 bottom
C1182  2.2uF  [0402]  188.01 47.01 0 bottom
C1183  2.2uF  [0402]  198.02 53.01 0 bottom
C1184  47uF  [0805]  198.82 51.51 0 bottom
C1185  100uF  [1206]  200.53 55.75 0 bottom
C1186  0.1uF  [0402]  197.52 49.51 270 bottom
C1187  0.1uF  [0402]  184.01 49.01 0 bottom
C1188  0.1uF  [0402]  198.52 42.5 90 bottom
C1189  0.1uF  [0402]  184.01 50.01 0 bottom
C1190  0.1uF  [0402]  199.02 48.01 180 bottom
C1191  2.2uF  [0402]  190.52 43.5 90 bottom
C1192  47uF  [0805]  188.21 43.5 180 bottom
C1193  2.2uF  [0402]  183.01 43 0 bottom
C1194  47uF  [0805]  180.09 42.55 180 bottom
C1197  0.1uF  [0402]  190.75 8.38 90 bottom
C1198  0.1uF  [0402]  198.37 22.86 90 bottom
C1199  0.1uF  [0402]  199.26 20.32 90 bottom
C1200  470pF  [0402]  194.31 8.38 90 bottom
C1201  0.1uF  [0402]  198.25 17.78 90 bottom
C1202  0.1uF  [0402]  184.78 17.78 90 bottom
C1203  470pF  [0402]  188.72 8.38 90 bottom
C1204  0.1uF  [0402]  183.77 20.32 90 bottom
C1205  1000pF  [1206]  179.96 14.1 270 top
C1206  1000pF  [1206]  203.07 14.1 270 top
C1207  0.33uF  [0603]  104.52 108.97 90 top
C1208  22uF  [1206]  105.92 110.36 90 bottom
C1209  22uF  [1206]  108.33 104.52 270 bottom
C1210  22uF  [1206]  105.92 104.52 270 bottom
C1211  1uF  [0603]  105.41 100.84 0 top
C1212  0.01uF  [0402]  101.22 108.46 270 top
C1213  1uF  [0603]  106.81 108.84 0 top
C1214  0.1uF  [0402]  99.06 103.38 270 top
C1215  470uF  [7343]  127.76 101.73 0 top
C1216  470uF  [7343]  127.76 107.06 0 top
C1217  47uF  [0805]  127.89 95.89 0 top
C1218  47uF  [0805]  127.89 98.04 0 top
C1219  510pF  [0402]  100.58 103.89 0 top
C1220  1uF  [0402]  104.01 102.49 90 bottom
C1221  0.01uF  [0402]  103 103.51 90 bottom
C1222  0.1uF  [0402]  129.79 114.94 0 top
C1223  0.1uF  [0402]  98.55 99.7 270 top
C1224  0.47uF  [0603]  214.63 61.46 0 top
C1225  1uF  [0603]  267.59 61.47 0 top
C1226  1uF  [0603]  206.5 60.57 90 top
C1227  1uF  [0603]  259.46 60.58 90 top
C1228  22uF  [1206]  210.19 60.06 180 bottom
C1229  22uF  [1206]  210.19 57.65 180 bottom
C1230  1uF  [0603]  214.5 59.17 90 top
C1231  0.01uF  [0402]  214.12 64.76 180 top
C1232  1uF  [0603]  267.46 59.18 90 top
C1233  22uF  [1206]  263.14 60.07 180 bottom
C1234  22uF  [1206]  263.14 57.66 180 bottom
C1235  0.01uF  [0402]  267.08 64.77 180 top
C1236  0.1uF  [0402]  206.38 51.55 90 bottom
C1237  47uF  [0805]  263.14 51.31 90 bottom
C1238  0.1uF  [0402]  259.33 51.56 90 bottom
C1239  0.1uF  [0402]  209.04 66.92 0 top
C1240  47uF  [0805]  210.19 51.3 90 bottom
C1241  47uF  [0805]  208.03 51.3 90 bottom
C1242  47uF  [0805]  260.99 51.31 90 bottom
C1243  0.1uF  [0402]  262 66.93 0 top
C1244  560pF  [0402]  209.55 65.4 90 top
C1245  680pF  [0402]  262.51 65.41 90 top
C1246  1uF  [0402]  208.15 61.97 0 bottom
C1247  0.01uF  [0402]  209.17 62.98 0 bottom
C1248  47uF  [0805]  212.34 51.3 90 bottom
C1249  47uF  [0805]  214.5 51.3 90 bottom
C1250  1uF  [0402]  261.11 61.98 0 bottom
C1251  0.01uF  [0402]  262.13 62.99 0 bottom
C1252  47uF  [0805]  265.3 51.31 90 bottom
C1253  47uF  [0805]  267.46 51.31 90 bottom
C1254  0.1uF  [0402]  179.45 163.7 270 top
C1255  0.1uF  [0402]  182.5 163.7 270 top
C1256  0.1uF  [0402]  174.75 163.7 270 top
C1257  0.1uF  [0402]  169.67 163.7 270 top
C1258  0.1uF  [0402]  167.13 163.7 270 top
C1259  0.1uF  [0402]  160.91 163.7 270 top
C1260  0.1uF  [0402]  158.37 163.7 270 top
C1261  0.1uF  [0402]  164.08 163.7 270 top
C1262  3000pF  [0402]  161.67 99.31 180 bottom
C1263  10uF  [0603]  152.65 113.16 180 bottom
C1264  1uF  [0402]  155.19 113.16 0 bottom
C1265  0.1uF  [0402]  176.91 200.53 180 top
C1266  0.1uF  [0402]  176.91 201.55 180 top
C1267  0.1uF  [0402]  198.88 113.41 180 top
C1268  0.1uF  [0402]  198.88 114.43 180 top
C1269  0.1uF  [0402]  91.82 202.82 0 top
C1270  0.1uF  [0402]  91.82 201.8 0 top
C1273  0.01uF  [0402]  108.08 147.19 180 bottom
C1274  0.1uF  [0402]  91.31 131.57 90 bottom
C1275  0.1uF  [0402]  97.28 126.49 0 bottom
C1276  0.1uF  [0402]  90.93 127.25 180 bottom
C1277  0.1uF  [0402]  95.38 127.25 45 bottom
C1278  10uF  [1206]  19.56 83.69 90 top
C1279  10uF  [1206]  17.15 83.69 90 top
C1280  0.1uF  [0603]  16.76 73.79 270 top
C1281  0.01uF  [0402]  18.03 73.91 270 top
C1282  4.7uF  [0603]  49.53 128.91 180 top
C1283  0.1uF  [0402]  49.66 126.62 180 top
C1284  0.1uF  [0402]  49.66 127.64 180 top
C1285  0.1uF  [0402]  247.78 60.58 270 top
C1286  0.1uF  [0402]  248.79 60.58 270 top
C1287  18pF  [0402]  229.74 46.1 0 top
C1288  18pF  [0402]  229.74 43.81 0 top
C1289  1uF  [0402]  261.37 46.48 180 top
C1290  2.2uF  [0402]  245.82 51.01 180 bottom
C1291  2.2uF  [0402]  243.82 51.01 180 bottom
C1292  100uF  [1206]  234.95 58.42 180 bottom
C1293  100uF  [1206]  253.24 46.48 0 bottom
C1294  2.2uF  [0402]  245.82 41 0 bottom
C1295  2.2uF  [0402]  245.82 50.01 0 bottom
C1296  2.2uF  [0402]  243.82 54.01 0 bottom
C1297  2.2uF  [0402]  243.82 53.01 180 bottom
C1298  100uF  [1206]  236.6 54.1 90 bottom
C1299  2.2uF  [0402]  243.82 50.01 0 bottom
C1300  2.2uF  [0402]  248.32 42.5 90 bottom
C1301  2.2uF  [0402]  243.82 44 0 bottom
C1302  47uF  [0805]  251.71 44.2 0 bottom
C1303  2.2uF  [0402]  243.82 52.01 0 bottom
C1304  2.2uF  [0402]  247.32 52.51 90 bottom
C1305  2.2uF  [0402]  247.32 49.51 270 bottom
C1306  2.2uF  [0402]  245.82 53.01 180 bottom
C1307  2.2uF  [0402]  247.82 41 0 bottom
C1308  2.2uF  [0402]  247.32 42.5 270 bottom
C1309  2.2uF  [0402]  246.32 42.5 90 bottom
C1310  2.2uF  [0402]  245.32 42.5 270 bottom
C1311  2.2uF  [0402]  245.82 52.01 0 bottom
C1312  2.2uF  [0402]  245.82 49.01 180 bottom
C1313  2.2uF  [0402]  243.82 49.01 180 bottom
C1314  2.2uF  [0402]  249.82 41 0 bottom
C1315  2.2uF  [0402]  245.32 39.5 90 bottom
C1316  2.2uF  [0402]  247.32 39.5 90 bottom
C1317  2.2uF  [0402]  243.82 41 0 bottom
C1318  2.2uF  [0402]  249.32 39.5 90 bottom
C1319  2.2uF  [0402]  243.32 39.5 90 bottom
C1320  47uF  [0805]  251.97 39.75 90 bottom
C1321  100uF  [1206]  254.25 40 90 bottom
C1322  2.2uF  [0402]  240.81 49.01 180 bottom
C1323  2.2uF  [0402]  245.82 47.01 0 bottom
C1324  2.2uF  [0402]  243.82 47.01 0 bottom
C1325  2.2uF  [0402]  240.81 50.01 0 bottom
C1326  2.2uF  [0402]  238.81 54.01 0 bottom
C1327  2.2uF  [0402]  238.81 53.01 180 bottom
C1328  0.01uF  [0402]  243.82 55.01 180 bottom
C1329  0.01uF  [0402]  246.82 54.01 180 bottom
C1330  2.2uF  [0402]  238.81 52.01 0 bottom
C1331  0.01uF  [0402]  238.81 55.01 180 bottom
C1332  0.01uF  [0402]  240.81 55.01 180 bottom
C1333  0.1uF  [0402]  240.81 56.01 180 bottom
C1334  0.1uF  [0402]  243.82 56.01 180 bottom
C1335  100uF  [1206]  243.71 59.69 90 bottom
C1336  100uF  [1206]  240.92 59.69 90 bottom
C1337  2.2uF  [0402]  240.81 51.01 180 bottom
C1338  2.2uF  [0402]  240.81 52.01 0 bottom
C1339  2.2uF  [0402]  238.81 51.01 180 bottom
C1340  2.2uF  [0402]  240.81 53.01 180 bottom
C1341  2.2uF  [0402]  240.81 54.01 0 bottom
C1342  2.2uF  [0402]  238.81 50.01 0 bottom
C1343  2.2uF  [0402]  238.81 47.01 0 bottom
C1344  2.2uF  [0402]  240.81 47.01 0 bottom
C1345  0.01uF  [0402]  245.82 55.01 180 bottom
C1346  0.01uF  [0402]  247.82 55.01 180 bottom
C1347  0.1uF  [0402]  247.82 56.01 180 bottom
C1348  100uF  [1206]  247.9 58.29 0 bottom
C1349  2.2uF  [0402]  248.82 54.01 180 bottom
C1350  2.2uF  [0402]  238.81 49.01 180 bottom
C1351  2.2uF  [0402]  248.82 53.01 0 bottom
C1352  47uF  [0805]  249.62 51.51 0 bottom
C1353  100uF  [1206]  251.33 55.75 0 bottom
C1354  0.1uF  [0402]  234.81 50.01 0 bottom
C1355  0.1uF  [0402]  249.32 42.5 90 bottom
C1356  0.1uF  [0402]  249.82 48.01 180 bottom
C1357  0.1uF  [0402]  248.32 49.51 270 bottom
C1358  0.1uF  [0402]  234.81 49.01 0 bottom
C1359  2.2uF  [0402]  241.32 43.5 90 bottom
C1360  47uF  [0805]  239.01 43.5 180 bottom
C1361  2.2uF  [0402]  233.81 43 0 bottom
C1362  47uF  [0805]  230.89 42.55 180 bottom
C1365  0.1uF  [0402]  241.55 8.38 90 bottom
C1366  0.1uF  [0402]  249.17 22.86 90 bottom
C1367  0.1uF  [0402]  249.05 17.78 90 bottom
C1368  470pF  [0402]  245.11 8.38 90 bottom
C1369  0.1uF  [0402]  250.06 20.32 90 bottom
C1370  0.1uF  [0402]  234.57 20.32 90 bottom
C1371  470pF  [0402]  239.52 8.38 90 bottom
C1372  0.1uF  [0402]  235.58 17.78 90 bottom
C1373  1000pF  [1206]  230.76 14.1 270 top
C1374  1000pF  [1206]  253.87 14.1 270 top
C1375  0.01uF  [0402]  234.7 97.41 0 top
C1376  0.01uF  [0402]  231.27 101.35 180 top
C1377  0.01uF  [0402]  234.7 105.28 0 top
C1378  0.1uF  [0402]  114.55 94.74 270 top
C1379  0.1uF  [0402]  111.51 94.74 90 bottom
C1380  0.1uF  [0402]  240.28 124.46 180 top
C1381  0.1uF  [0402]  240.28 123.19 180 top
C1382  0.1uF  [0402]  156.21 74.3 0 top
C1383  0.1uF  [0402]  226.44 128.02 270 top
C1384  0.1uF  [0402]  156.21 73.28 0 top
C1385  0.1uF  [0402]  225.42 128.02 270 top
C1386  0.1uF  [0402]  262 121.29 270 top
C1387  0.1uF  [0402]  160.27 69.72 0 top
C1388  0.1uF  [0402]  260.99 121.29 270 top
C1389  0.1uF  [0402]  160.27 68.71 0 top
C1390  0.1uF  [0402]  259.21 108.59 270 top
C1391  0.1uF  [0402]  263.78 108.59 270 top
C1392  0.1uF  [0402]  233.93 126.49 0 top
C1393  0.1uF  [0402]  237.74 120.14 0 top
D1  GRN  [LED_0603]  71.63 91.69 90 top
D3  CMHD3595  [SOD123]  98.93 23.62 180 top
D4  CMHD3595  [SOD123]  105.28 27.94 90 top
D33  BAT43WS  [SOD323]  58.17 135.25 270 top
D34  RB521  [SOD523]  58.42 126.75 180 top
D35  RB521  [SOD523]  15.62 62.99 0 top
D43  GRN  [LED_PM_1S]  27.81 1.14 0 top
D44  GRN  [LED_PM_1S]  23.49 1.14 0 top
F9  500mA  [1206]  220.73 241.05 0 top
F10  500mA  [1206]  64.26 137.79 0 top
F11  500mA  [1206]  246.13 241.05 0 top
F12  500mA  [1206]  233.43 241.05 0 top
F13  500mA  [1206]  258.83 241.05 0 top
F14  500mA  [1206]  258.44 80.9 180 top
F15  500mA  [1206]  233.68 80.9 180 top
FB6  BLM21PG121SN1  [0805]  106.42 19.56 90 top
FB7  BLM21PG121SN1  [0805]  113.53 19.56 90 bottom
FB8  BLM21PG121SN1  [0805]  104.39 19.56 90 top
FB9  BLM21PG121SN1  [0805]  113.53 19.56 90 top
FB10  BLM18BD601SN1  [0603]  80.14 89.66 90 top
FB11  BLM18PG121SN1  [0603]  161.92 97.28 270 bottom
FB12  BLM18PG121SN1  [0603]  159.64 98.04 0 bottom
FB13  BLM18PG121SN1  [0603]  156.59 98.04 180 bottom
FB18  BLM18BD601SN1  [0603]  122.94 39.5 0 top
FB19  BLM18BD601SN1  [0603]  122.94 36.45 0 top
FB20  BLM18BD601SN1  [0603]  122.94 37.97 0 top
FB21  BLM18BD601SN1  [0603]  122.94 34.92 0 top
FB22  BLM18BD601SN1  [0603]  122.94 30.35 0 top
FB23  BLM18BD601SN1  [0603]  122.94 31.88 0 top
FB24  BLM18BD601SN1  [0603]  122.94 28.83 0 top
FB25  BLM18BD601SN1  [0603]  122.94 33.4 0 top
FB26  BLM18BD601SN1  [0603]  166.24 43.56 0 top
FB29  BLM18BD601SN1  [0603]  135 41.66 270 top
FB47  BLM18BD601SN1  [0603]  47.88 112.65 0 top
FB48  BLM18BD601SN1  [0603]  80.14 98.17 90 top
FB50  BLM18BD601SN1  [0603]  80.14 106.55 90 top
FB52  BLM18BD601SN1  [0603]  153.16 71.76 0 top
FB54  BLM18PG221SN1  [0603]  232.16 134.62 270 bottom
FB55  BLM18PG221SN1  [0603]  232.16 131.57 270 bottom
FB56  MPZ2012S101A  [0805]  187.83 59.05 90 bottom
FB57  MPZ2012S101A  [0805]  190.52 45.5 0 bottom
FB58  MPZ2012S601A  [0805]  180.85 39.62 270 bottom
FB59  BLM18BD601SN1  [0603]  192.02 8.89 90 bottom
FB60  BLM15AG601SN1  [0402]  147.07 45.21 270 top
FB61  BLM15AG601SN1  [0402]  148.08 45.21 270 top
FB62  BLM15AG601SN1  [0402]  152.53 42.04 270 top
FB63  BLM15AG601SN1  [0402]  151.51 42.04 270 top
FB64  MPZ2012S101A  [0805]  238.63 59.05 90 bottom
FB65  MPZ2012S101A  [0805]  241.32 45.5 0 bottom
FB66  MPZ2012S601A  [0805]  231.65 39.62 270 bottom
FB67  BLM18BD601SN1  [0603]  242.82 8.89 90 bottom
FB68  MPZ2012S101A  [0805]  199.82 49.5 0 bottom
FB69  MPZ2012S101A  [0805]  250.62 49.5 0 bottom
FB70  BLM18BD601SN1  [0603]  257.81 108.59 90 top
FB71  BLM18BD601SN1  [0603]  231.27 126.75 0 top
J1  DDR3_DIMM  [CON_DDR3_DIMM]  153.42 158.5 0 top
J2  SD_CARD_SKT  [CON_SD]  39.02 1.02 180 bottom
J3  HTST-108-01-L-DV  [HDR_P254_HTST_2X8]  11.18 138.18 180 top
J9  JMP2  [JMP_P254_T_1X2]  57.53 148.34 270 top
J10  JMP2  [JMP_P254_T_1X2]  57.53 145.16 270 top
J11  JMP2  [JMP_P254_T_1X2]  57.53 151.51 270 top
J13  RJ45_2X1  [CON_RJ45_2X1]  141.02 -1.48 0 top
J14  RJ45_LED_2X1  [CON_RJ45_2X1_LED]  159.52 -1.48 0 top
J18  PCIE_X1  [CON_PEX1]  272.8 93.73 90 top
J19  MINIPCIE_CONN  [CON_MINIPCIE]  183.9 201.68 90 top
J20  MINIPCIE_CONN  [CON_MINIPCIE]  84.84 201.68 270 top
J26  HDR_2X5  [HDR_P254_M_T_2X5]  16.89 124.21 270 top
J33  CON_3PIN  [CON_WAFER_P254_S_1X3]  222 245.49 180 top
J34  CON_3PIN  [CON_WAFER_P254_S_1X3]  66.55 132.33 90 top
J35  JMP2  [JMP_P254_T_1X2]  66.55 126.37 270 top
J37  ATX_PWR_CONN_20PIN  [CON_ATX_20PIN]  10.54 94.36 270 top
J41  USB_A_2  [CON_USB_A_2]  109.02 -0.98 0 top
J43  CONN_2X20  [CON_MEC6_120]  272.8 152.06 0 top
J44  CON_3PIN  [CON_WAFER_P254_S_1X3]  247.4 245.49 180 top
J45  CON_3PIN  [CON_WAFER_P254_S_1X3]  234.7 245.49 180 top
J46  CON_3PIN  [CON_WAFER_P254_S_1X3]  260.1 245.49 180 top
J47  HDR_1X2  [JMP_P254_T_1X2]  12.45 56.9 0 top
J48  HDR_1X2  [JMP_P254_T_1X2]  6.73 56.9 0 top
J49  BAT_SOCKET  [CON_BAT_WBA3B2]  91.19 150.24 180 top
J50  JT4-1108HL  [CON_RJ45_XG_1X1_LED]  191.52 -1.52 0 top
J51  HDR_1X7  [HDR_P254_M_T_1X7]  173.35 66.42 0 top
J52  HDR_1X3  [HDR_P254_M_T_1X3]  176.66 51.18 180 top
J53  JMP3  [JMP_P254_T_1X3]  40.89 43.94 270 top
J54  HDR_1X3  [HDR_P254_M_T_1X3]  227.46 51.18 180 top
J55  HDR_1X7  [HDR_P254_M_T_1X7]  224.16 66.42 0 top
